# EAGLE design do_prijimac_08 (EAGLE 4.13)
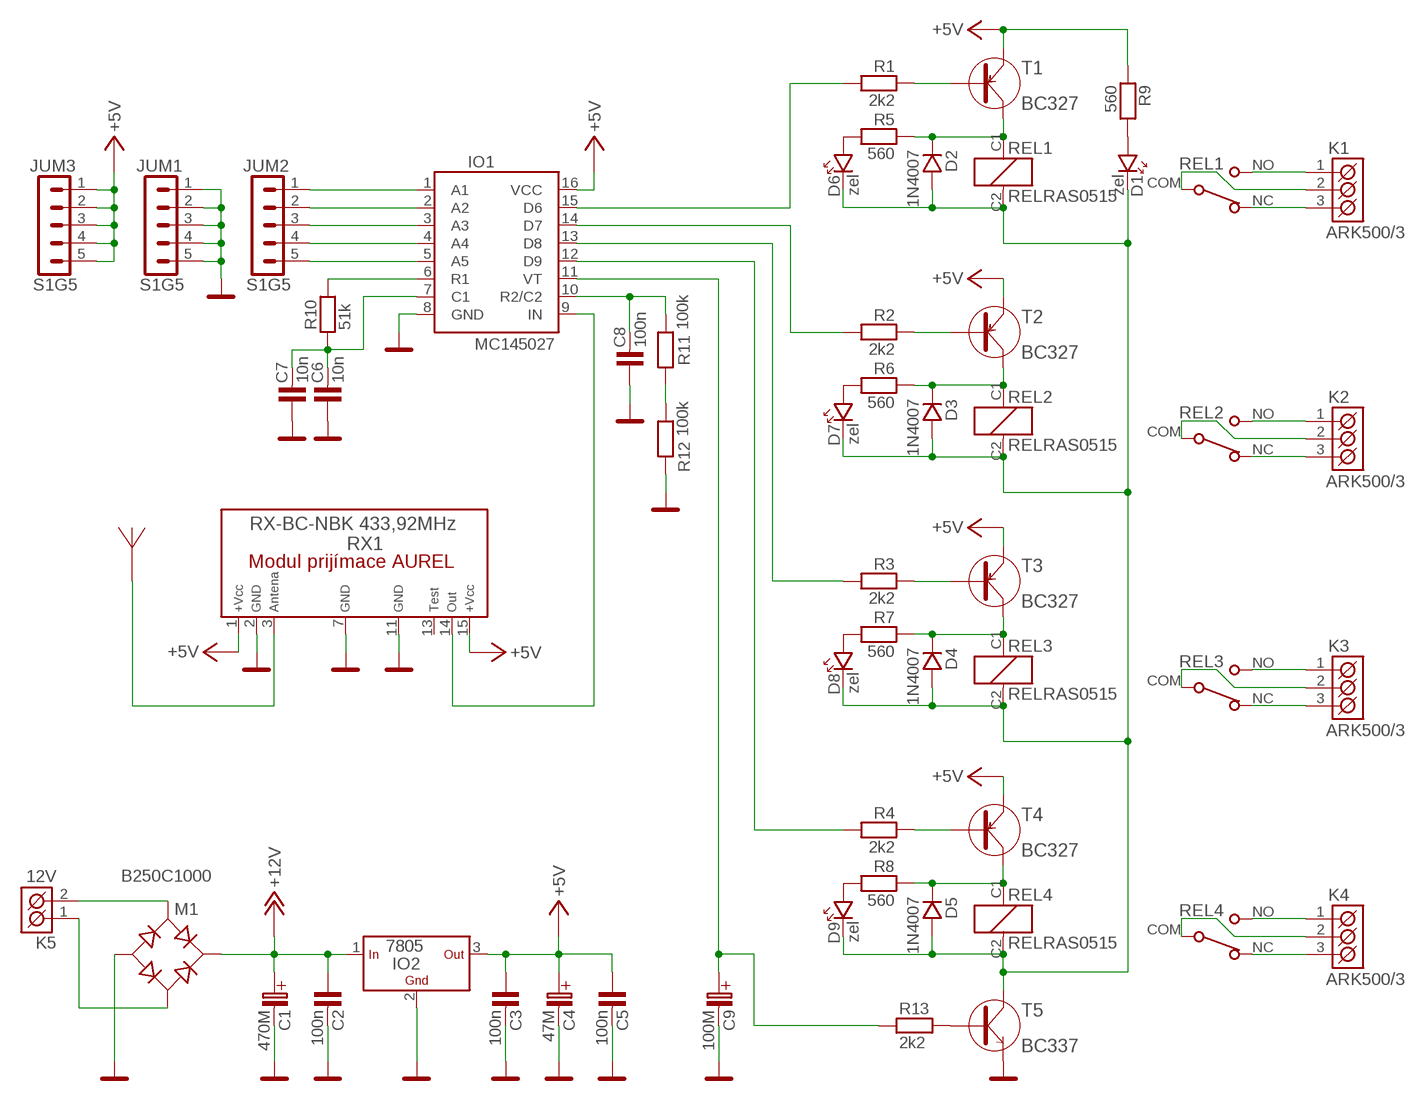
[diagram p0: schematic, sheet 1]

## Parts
ANT1  ANTENA  [PAD_1]
C1  470M  C-ELEKTROLYT_5  [C-EL_5]
C2  100n  C-KERAMIK_5  [C-5]
C3  100n  C-KERAMIK_5  [C-5]
C4  47M  C-ELEKTROLYT_2  [C-EL_2]
C5  100n  C-KERAMIK_SMD_1206  [1206]
C6  10n  C-KERAMIK_SMD_1206  [1206]
C7  10n  C-KERAMIK_SMD_1206  [1206]
C8  100n  C-KERAMIK_SMD_1206  [1206]
C9  100M  C-ELEKTROLYT_2  [C-EL_2]
D1  zel  LED_SMD_1206  [P1206]
D2  1N4007  1N4007_SMD_SM-1  [SM-1]
D3  1N4007  1N4007_SMD_SM-1  [SM-1]
D4  1N4007  1N4007_SMD_SM-1  [SM-1]
D5  1N4007  1N4007_SMD_SM-1  [SM-1]
D6  zel  LED_3  [LED_3]
D7  zel  LED_3  [LED_3]
D8  zel  LED_3  [LED_3]
D9  zel  LED_3  [LED_3]
IO1  MC145027  [DIL16]
IO2  7805  78_LEZ_LEZ  [TO-220]
JUM1  S1G5  S1G5_JUMP  [S1G5_JUM]
JUM2  S1G5  S1G5_JUMP  [S1G5_JUM]
JUM3  S1G5  S1G5_JUMP  [S1G5_JUM]
K1  ARK500/3  [ARK500/3]
K2  ARK500/3  [ARK500/3]
K3  ARK500/3  [ARK500/3]
K4  ARK500/3  [ARK500/3]
K5  12V  ARK500/2  [ARK500/2]
M1  B250C1000  BC1000  [DM_DB1]
R1  2k2  R_SMD_1206  [1206]
R2  2k2  R_SMD_1206  [1206]
R3  2k2  R_SMD_1206  [1206]
R4  2k2  R_SMD_1206  [1206]
R5  560  R_SMD_1206  [1206]
R6  560  R_SMD_1206  [1206]
R7  560  R_SMD_1206  [1206]
R8  560  R_SMD_1206  [1206]
R9  560  R_SMD_1206  [1206]
R10  51k  R_SMD_1206  [1206]
R11  100k  R_SMD_1206  [1206]
R12  100k  R_SMD_1206  [1206]
R13  2k2  R_SMD_1206  [1206]
REL1  RELRAS0515  RELRAS15  [RELE_RAS]
REL2  RELRAS0515  RELRAS15  [RELE_RAS]
REL3  RELRAS0515  RELRAS15  [RELE_RAS]
REL4  RELRAS0515  RELRAS15  [RELE_RAS]
RX1  RX-BC-NBK433  [RX-BC-NB]
T1  BC327  [TO-92]
T2  BC327  [TO-92]
T3  BC327  [TO-92]
T4  BC327  [TO-92]
T5  BC337  [TO-92]

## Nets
+5V: C3.1 C4.C+(C_EL+) C5.1 IO1.16(VCC) IO2.3(OUT) JUM3.1 JUM3.2 JUM3.3 JUM3.4 JUM3.5 R9.1 RX1.1(+5V) RX1.15(+5V) T1.3(E) T2.3(E) T3.3(E) T4.3(E)
+12V: C1.C+(C_EL+) C2.1 IO2.1(IN) M1.+
GND: C1.C-(C_EL-) C2.2 C3.2 C4.C-(C_EL-) C5.2 C6.1 C7.1 C8.1 C9.C-(C_EL-) IO1.8(GND) IO2.2(GND) JUM1.1 JUM1.2 JUM1.3 JUM1.4 JUM1.5 M1.- R12.1 RX1.2(GND) RX1.7(GND) RX1.11(GND) T5.3(E)
N$1: IO1.1(A1) JUM2.1
N$2: IO1.2(A2) JUM2.2
N$3: IO1.3(A3) JUM2.3
N$4: IO1.4(A4) JUM2.4
N$5: IO1.5(A5) JUM2.5
N$6: C6.2 C7.2 IO1.7(C1) R10.1
N$7: R11.1 R12.2
N$8: IO1.6(R1) R10.2
N$9: C8.2 IO1.10(R2/C2) R11.2
N$10: K5.1(K1) M1.AC2
N$11: K5.2(K2) M1.AC1
N$13: ANT1.1 RX1.3(ANTENA)
N$14: IO1.9(IN) RX1.14(OUT)
N$15: C9.C+(C_EL+) IO1.11(VT) R13.1
N$16: D1.A R9.2
N$21: R4.1 T4.2(B)
N$22: R3.1 T3.2(B)
N$23: R1.1 T1.2(B)
N$24: R2.1 T2.2(B)
N$25: IO1.15(D6) R1.2
N$26: IO1.14(D7) R2.2
N$27: IO1.13(D8) R3.2
N$28: IO1.12(D9) R4.2
N$32: K1.3(K3) REL1.NC(SW:NC)
N$33: K1.2(K2) REL1.COM(SW:COM)
N$34: K1.1(K1) REL1.NO(SW:NO)
N$35: K2.1(K1) REL2.NO(SW:NO)
N$36: K2.2(K2) REL2.COM(SW:COM)
N$37: K2.3(K3) REL2.NC(SW:NC)
N$41: D6.A R5.2
N$42: D7.A R6.2
N$43: D8.A R7.2
N$44: D9.A R8.2
N$45: K3.1(K1) REL3.NO(SW:NO)
N$46: K3.2(K2) REL3.COM(SW:COM)
N$47: K3.3(K3) REL3.NC(SW:NC)
N$51: K4.1(K1) REL4.NO(SW:NO)
N$52: K4.2(K2) REL4.COM(SW:COM)
N$53: K4.3(K3) REL4.NC(SW:NC)
N$58: D2.K R5.1 REL1.C1(RE:C1) T1.1(C)
N$61: R13.2 T5.2(B)
N$62: D1.K D2.A D3.A D4.A D5.A D6.K D7.K D8.K D9.K REL1.C2(RE:C2) REL2.C2(RE:C2) REL3.C2(RE:C2) REL4.C2(RE:C2) T5.1(C)
N$63: D3.K R6.1 REL2.C1(RE:C1) T2.1(C)
N$64: D4.K R7.1 REL3.C1(RE:C1) T3.1(C)
N$65: D5.K R8.1 REL4.C1(RE:C1) T4.1(C)
Unconnected: RX1.13(MER_BOD)

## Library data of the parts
ANT1 = #PaJa_15:ANTENA: SCH symbol - Anteny + pajeci bod na DPS
C1 C4 = #PaJa_15:C-ELEKTROLYT: Kondenzator - elektrolyticky
C2 C3 C5-C8 = #PaJa_15:C-KERAMIK: Kondenzator - keramicky
C9 = #PaJa_17:C-ELEKTROLYT: Kondenzator - elektrolyticky
D1 D6-D9 = #PaJa_15:LED: LED - jednobarevna
D2-D5 = #PaJa_15:1N4007: Usmernovaci dioda - 1A, 1000V
IO1 = #PaJa_15:MC145027
IO2 = #PaJa_15:78??: Stabilizátor - 1A a 1,5A ?? - napeti => 05, 06, 08, 09, 12, 15, 18, 20, 24 => 1,5A ?? - napeti => 10, 12, 15, 18 => 1A
JUM1-JUM3 = #PaJa_15:S1G5_JUMP: Radove konektory - koliky - 5x
K1-K4 = #PaJa_15:ARK500/3: Svorkovnice - roztec 5mm - trojita
K5 = #PaJa_15:ARK500/2: Svorkovnice - roztec 5mm - dvojita
M1 = #PaJa_16:B???C1000: Diodovy mustek - 250V nebo 380V, 1A
R1-R12 = #PaJa_15:R: Rezistor
R13 = #PaJa_16:R: Rezistor
REL1-REL4 = #PaJa_19:RELRAS??15: RELE - 1x prepinaci, 5V, 12V, 24V max. spinany proud = 15A
RX1 = #PaJa_16:RX-BC-NBK433: Modul prijimace AUREL - 433,92 MHz
T1-T4 = #PaJa_17:BC327: Tranzistor PNP - Univerzalni NF - Ic=0,5A
T5 = #PaJa_16:BC337: Tranzistor NPN - Univerzalni NF - Ic=0,5A

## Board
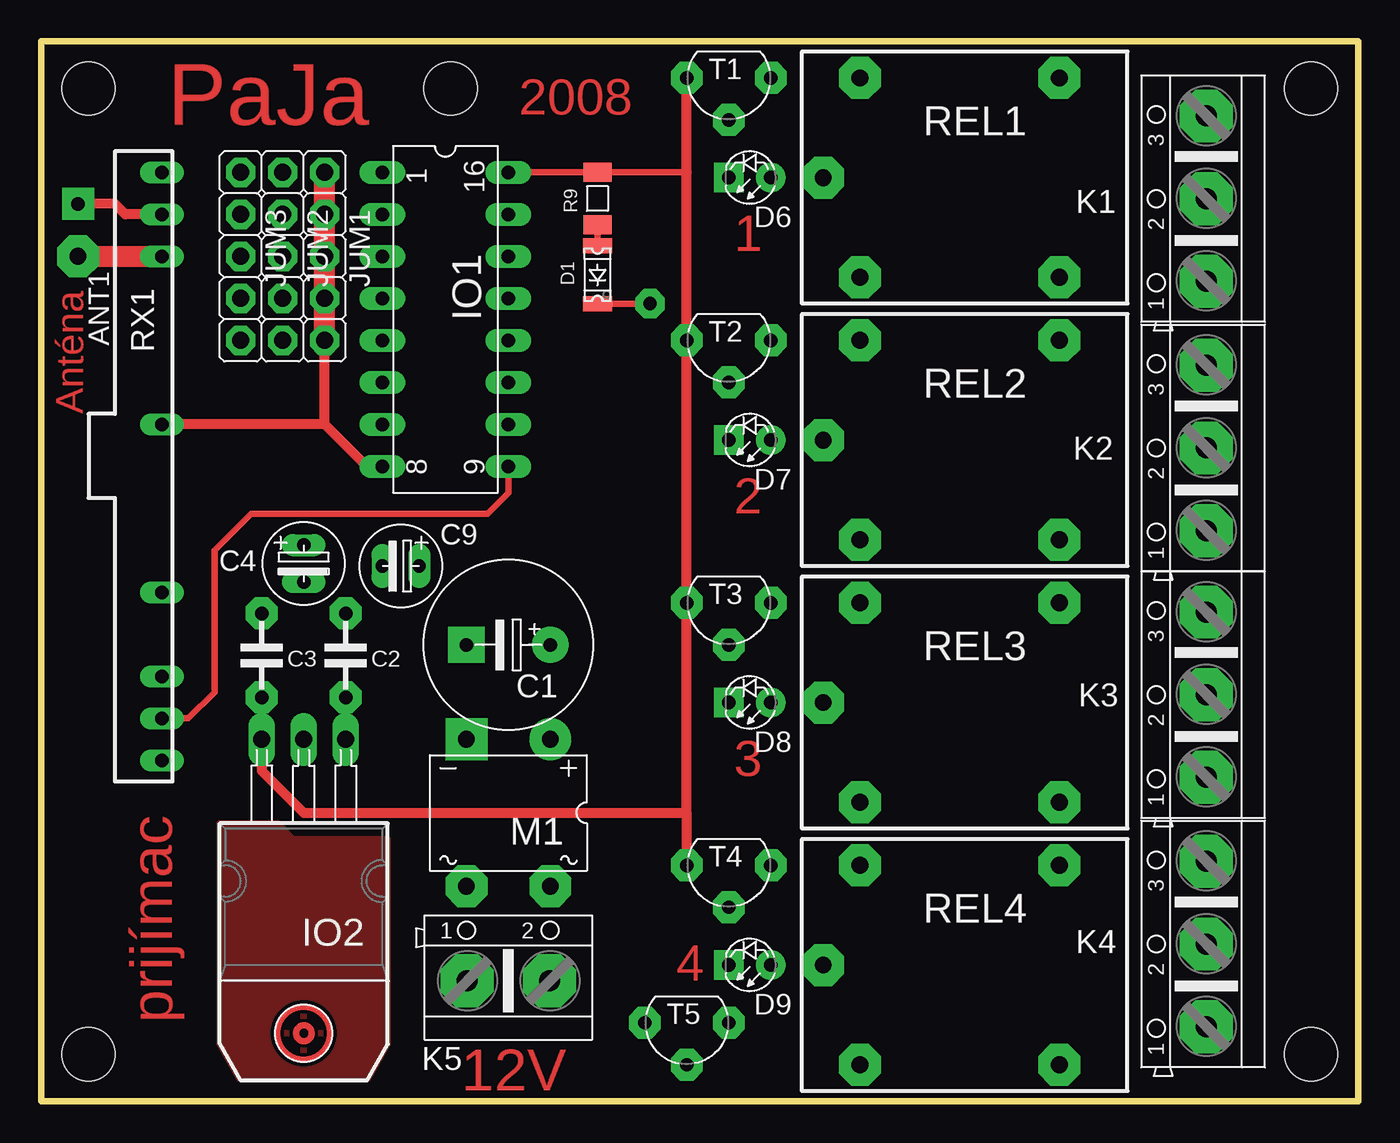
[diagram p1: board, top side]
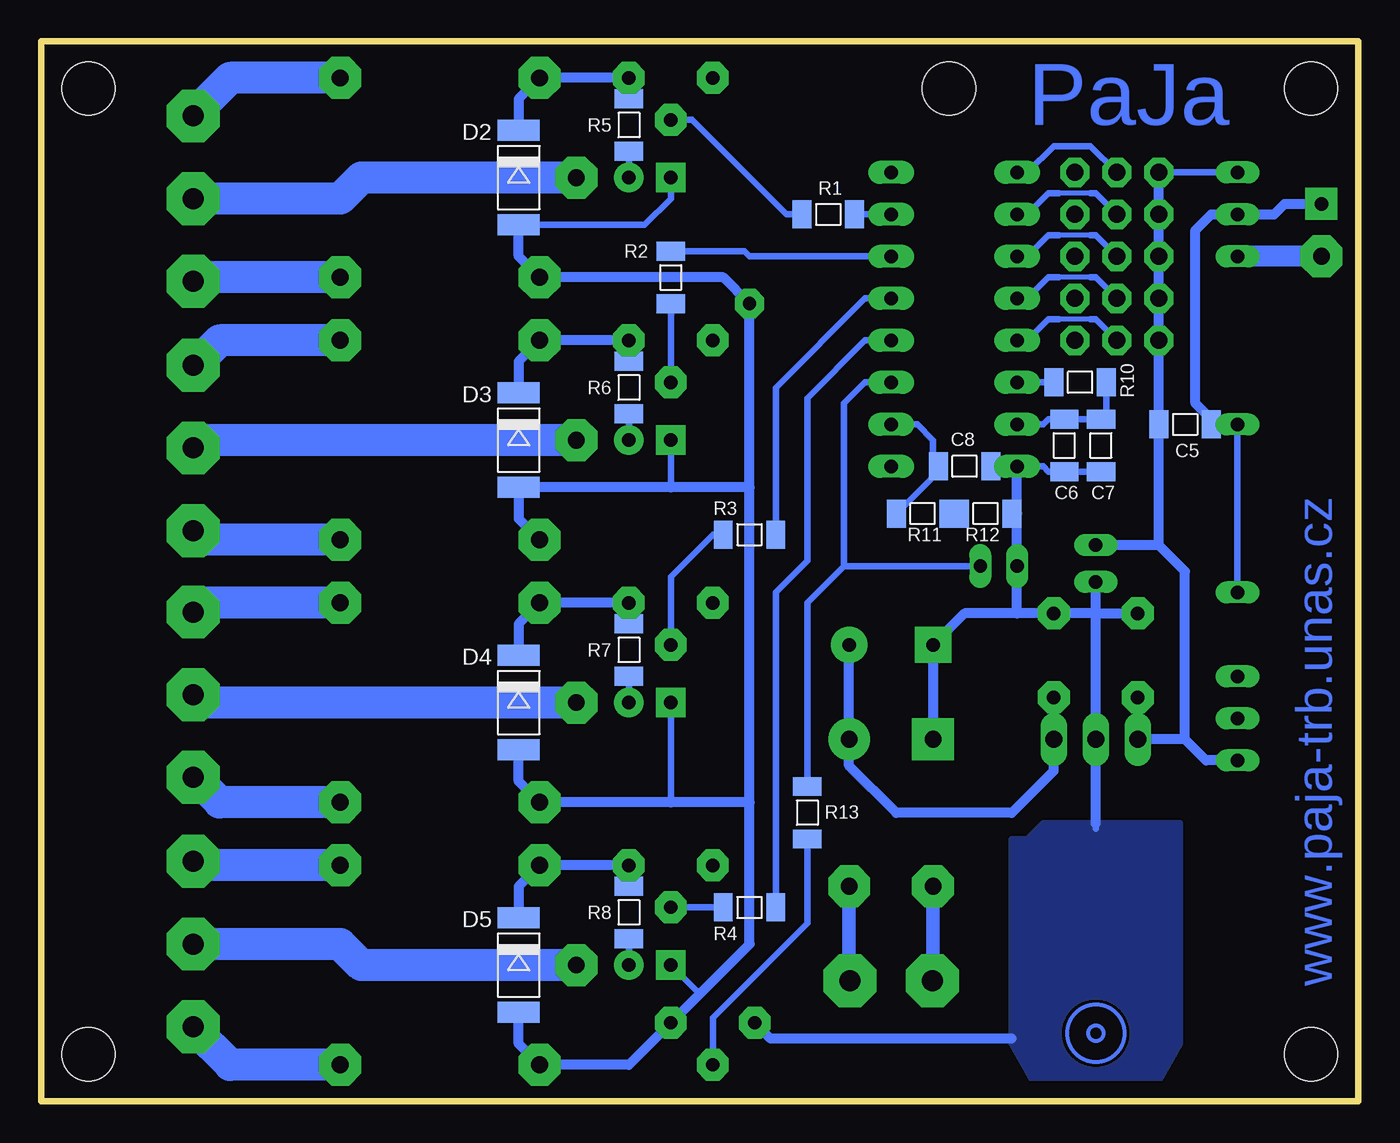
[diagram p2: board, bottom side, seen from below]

Size 79.68 x 64.12 mm. Coordinates in mm from the lower left corner, seen from the top.
Outline: 0,0 79.68,0 79.68,64.12 0,64.12 0,0
Copper layers (1*16): Top 0.035mm / dielectric 1.5mm / Bottom 0.035mm
Design rules "default": minimum track width 10mil, minimum drill 24mil, track to track 8mil, track to pad 8mil, pad to pad 8mil, via to via 8mil, smd to smd 8mil, copper to edge 40mil, drill to drill 8mil, minimum pad ring 10mil, minimum via ring 8mil, stop-mask expansion 4mil, vias tented up to drill 0mil, thermal gap 10mil
Holes 3.2 mm at 2.86,2.86 2.86,61.28 76.83,61.28 76.83,2.86 24.77,61.28

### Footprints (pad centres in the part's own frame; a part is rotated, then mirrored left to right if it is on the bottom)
PAD_1 = drill 1.016 pad 2.54 octagon: 1 0,0
C-EL_5 = drill 0.813 pad 2.184 round: C+ -2.54,0 | drill 0.813 pad 2.184 square: C- 2.54,0
C-5 = drill 0.813 pad 1.93 octagon: 1 -2.54,0; 2 2.54,0
C-EL_2 = drill 0.813 pad 1.27 long: C+ 0,0; C- 2.223,0
1206 = smd 1.143 x 1.702: 1 -1.587,0; 2 1.587,0
P1206 = smd 0.914 x 1.778: A 1.905,0; K -1.587,0
SM-1 = smd 1.27 x 2.54: A 2.54,0; K -3.175,0
LED_3 = drill 0.813 pad 1.778 round: A -1.27,0 | drill 0.813 pad 1.778 square: K 1.27,0
DIL16 = drill 0.813 pad 1.4 long: 1 -8.89,-3.81; 2 -6.35,-3.81; 3 -3.81,-3.81; 4 -1.27,-3.81; 5 1.27,-3.81; 6 3.81,-3.81; 7 6.35,-3.81; 8 8.89,-3.81; 9 8.89,3.81; 10 6.35,3.81; 11 3.81,3.81; 12 1.27,3.81; 13 -1.27,3.81; 14 -3.81,3.81; 15 -6.35,3.81; 16 -8.89,3.81
TO-220 = drill 1.016 pad 1.6 long: 1 -2.54,0; 2 0,0; 3 2.54,0
S1G5_JUM = drill 1.016 pad 1.778 octagon: 1 -5.08,0; 2 -2.54,0; 3 0,0; 4 2.54,0; 5 5.08,0
ARK500/3 = drill 1.27 pad 3.2 octagon: 1 -5,0; 2 0,0; 3 5,0
ARK500/2 = drill 1.27 pad 3.2 octagon: 1 -2.5,0; 2 2.5,0
DM_DB1 = drill 1.016 pad 2.54 round: + -2.54,-4.445 | drill 1.016 pad 2.54 square: - 2.54,-4.445 | drill 1.016 pad 2.54 octagon: AC1 -2.54,4.445; AC2 2.54,4.445
RELE_RAS = drill 1.016 pad 2.54 octagon: C1 -6.35,6.032; C2 -6.35,-6.032; COM -8.572,0; NC 5.715,6.032; NO 5.715,-6.032
RX-BC-NB = drill 0.813 pad 1.27 long: 1 -17.78,0; 2 -15.24,0; 3 -12.7,0; 7 -2.54,0; 11 7.62,0; 13 12.7,0; 14 15.24,0; 15 17.78,0
TO-92 = drill 0.813 pad 1.93 octagon: 1 0,2.54; 2 2.54,0; 3 0,-2.54

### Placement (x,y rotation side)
ANT1  2.22,51.12 0 top
C1  28.26,27.62 180 top
C2  18.41,26.99 90 top
C3  13.34,26.99 90 top
C4  15.88,33.66 270 top
C5  10.48,40.96 0 bottom
C6  17.78,39.69 90 bottom
C7  15.56,39.69 90 bottom
C8  23.81,38.42 180 bottom
C9  22.86,32.38 180 top
D1  33.66,49.85 90 top
D2  50.8,55.56 270 bottom
D3  50.8,39.69 270 bottom
D4  50.8,23.81 270 bottom
D5  50.8,7.94 270 bottom
D6  42.86,55.88 180 top
D7  42.86,40.01 180 top
D8  42.86,24.13 180 top
D9  42.86,8.26 180 top
IO1  24.45,47.31 270 top
IO2  15.88,21.91 180 top
JUM1  17.14,51.12 270 top
JUM2  14.61,51.12 270 top
JUM3  12.06,51.12 270 top
K1  70.48,54.61 90 top
K2  70.48,39.53 90 top
K3  70.48,24.61 90 top
K4  70.48,9.52 90 top
K5  28.26,7.3 0 top
M1  28.26,17.46 180 top
R1  32.07,53.66 0 bottom
R2  41.59,49.85 90 bottom
R3  36.83,34.29 0 bottom
R4  36.83,11.75 0 bottom
R5  44.13,59.05 270 bottom
R6  44.13,43.18 270 bottom
R7  44.13,27.3 270 bottom
R8  44.13,11.43 270 bottom
R9  33.66,54.61 270 top
R10  16.83,43.5 180 bottom
R11  26.35,35.56 180 bottom
R12  22.54,35.56 180 bottom
R13  33.34,17.46 270 bottom
REL1  55.88,55.88 0 top
REL2  55.88,40.01 0 top
REL3  55.88,24.13 0 top
REL4  55.88,8.26 0 top
RX1  7.3,38.42 270 top
T1  41.59,61.91 270 top
T2  41.59,46.04 270 top
T3  41.59,30.16 270 top
T4  41.59,14.29 270 top
T5  39.05,4.76 270 top

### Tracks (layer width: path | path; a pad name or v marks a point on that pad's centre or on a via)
+5V
  Top 0.406: IO1.16 R9.1 39.05,56.2
  Top 0.61: 39.05,17.46 15.88,17.46 13.34,20 IO2.3 | T1.3 39.05,56.2 T2.3 T3.3 39.05,17.46 | 39.05,17.46 T4.3
  Bottom 0.406: JUM3.1 RX1.1
  Bottom 0.61: JUM3.5 JUM3.4 JUM3.3 JUM3.2 JUM3.1 | RX1.15 9.21,20.64 10.48,21.91 | 10.48,21.91 10.48,32.07 12.06,33.66 | C3.1 IO2.3 10.48,21.91 | 12.06,33.66 C4.C+ | 12.06,33.66 C5.1 | C5.1 JUM3.5 | C5.1 JUM3.5
+12V
  Bottom 0.61: C1.C+ M1.+ 30.8,20.32 27.94,17.46 20.95,17.46 18.41,20 IO2.1 C2.1
GND  (via drill 0.81 pad 1.93)
  Top 0.61: 17.14,40.96 JUM1.5 | 17.14,40.96 19.68,38.42 IO1.8 | 17.14,40.96 RX1.7 | RX1.2 5.08,53.66 4.45,54.29 v2.22,54.29
  Top 1.27: JUM1.1 JUM1.2 JUM1.3 JUM1.4 JUM1.5
  Bottom 0.406: C7.1 C6.1 18.73,38.1 19.05,38.42 IO1.8 C8.1 | RX1.11 RX1.7 8.57,40.96 C5.2 | 15.88,16.83 15.88,16.51
  Bottom 0.61: 15.88,16.83 IO2.2 15.88,29.53 | 15.88,29.53 C4.C- | T5.3 35.56,3.81 20.95,3.81 | 15.88,29.53 C3.2 | 15.88,29.53 C2.2 20.64,29.53 | M1.- C1.C- 23.81,29.53 20.64,29.53 | 20.64,29.53 C9.C- 20.64,35.56 | 20.64,35.56 R12.1 | 20.64,35.56 IO1.8 | 8.57,40.96 9.84,42.23 9.84,52.7 8.89,53.66 RX1.2 5.08,53.66 4.45,54.29 v2.22,54.29
  pour Bottom: 10.79,16.83 19.05,16.83 20,15.88 20.95,15.88 20.95,3.49 19.68,1.27 12.06,1.27 10.79,3.49
N$1
  Bottom 0.406: IO1.1 20,56.2 18.41,57.78 16.19,57.78 JUM2.1
N$2
  Bottom 0.305: 16.19,54.93 18.1,54.93
  Bottom 0.406: IO1.2 20,53.66 18.73,54.93 18.1,54.93 | JUM2.2 15.88,54.93 16.19,54.93
N$3
  Bottom 0.305: 16.19,52.39 18.1,52.39
  Bottom 0.406: IO1.3 20,51.12 18.73,52.39 18.1,52.39 | JUM2.3 15.88,52.39 16.19,52.39
N$4
  Bottom 0.305: 16.19,49.85 18.1,49.85
  Bottom 0.406: IO1.4 20,48.58 18.73,49.85 18.1,49.85 | JUM2.4 15.88,49.85 16.19,49.85
N$5
  Bottom 0.305: 16.19,47.31 18.1,47.31
  Bottom 0.406: IO1.5 20,46.04 18.73,47.31 18.1,47.31 | JUM2.5 15.88,47.31 16.19,47.31
N$6
  Bottom 0.406: R10.1 15.24,41.27 C7.2 C6.2 18.73,41.27 19.05,40.96 IO1.7
N$7
  Bottom 0.406: R12.2 R11.1
N$8
  Bottom 0.406: R10.2 IO1.6
N$9
  Bottom 0.406: R11.2 25.4,38.1 C8.2 25.72,38.42 25.72,40.01 26.67,40.96 IO1.10
N$10
  Bottom 0.813: K5.1 25.76,7.58 25.72,7.62 M1.AC2
N$11
  Bottom 0.813: K5.2 30.8,7.3 M1.AC1
N$12
  pour Top: 10.79,16.83 14.29,16.83 15.24,15.88 20.95,15.88 20.95,3.49 19.68,1.27 12.06,1.27 10.79,3.49
N$13
  Top 1.27: ANT1.1 RX1.3
  Bottom 1.27: ANT1.1 RX1.3
N$14
  Top 0.406: IO1.9 28.26,36.83 26.99,35.56 12.7,35.56 10.48,33.34 10.48,24.77 8.89,23.18 RX1.14
N$15
  Bottom 0.406: IO1.11 29.84,43.5 31.11,42.23 31.11,32.38 | 31.11,32.38 C9.C+ | R13.1 33.34,30.16 31.11,32.38
N$16
  Top 0.406: D1.A | D1.A R9.2
N$21
  Bottom 0.406: R4.1 T4.2
N$22
  Bottom 0.406: R3.1 39.05,34.29 41.59,31.75 T3.2
N$23
  Bottom 0.406: R1.1 34.61,53.66 40.32,59.37 T1.2
N$24
  Bottom 0.406: T2.2 R2.1
N$25
  Bottom 0.406: IO1.15 R1.2
N$26
  Bottom 0.406: R2.2 37.15,51.44 36.83,51.12 IO1.14
N$27
  Bottom 0.406: IO1.13 29.84,48.58 35.24,43.18 R3.2
N$28
  Bottom 0.406: R4.2 35.24,30.8 33.34,32.7 33.34,42.55 29.84,46.04 IO1.12
N$32
  Bottom 1.93: K1.3 70.48,59.69 68.26,61.91 REL1.NC
N$33
  Bottom 1.93: REL1.COM 60.33,55.88 61.59,54.61 K1.2
N$34
  Bottom 1.93: K1.1 70.48,49.53 70.17,49.85 REL1.NO
N$35
  Bottom 1.93: K2.1 70.48,34.61 69.85,33.97 REL2.NO
N$36
  Bottom 1.93: K2.2 70.48,39.37 69.85,40.01 REL2.COM
N$37
  Bottom 1.93: K2.3 70.48,44.45 68.9,46.04 REL2.NC
N$41
  Bottom 0.406: D6.A R5.2
N$42
  Bottom 0.406: D7.A R6.2
N$43
  Bottom 0.406: D8.A R7.2
N$44
  Bottom 0.406: D9.A R8.2
N$45
  Bottom 1.93: K3.1 70.48,19.68 68.9,18.1 REL3.NO
N$46
  Bottom 1.93: K3.2 70.48,24.45 70.17,24.13 REL3.COM
N$47
  Bottom 1.93: K3.3 70.48,29.53 69.85,30.16 REL3.NC
N$51
  Bottom 1.93: K4.1 70.48,4.45 68.26,2.22 REL4.NO
N$52
  Bottom 1.93: REL4.COM 60.33,8.26 61.59,9.53 K4.2 | K4.2
N$53
  Bottom 1.93: K4.3 70.48,14.61 70.17,14.29 REL4.NC
N$58
  Bottom 0.406: R5.1 T1.1
  Bottom 0.61: D2.K 50.8,60.64 REL1.C1 T1.1
N$61
  Bottom 0.406: R13.2 33.34,10.79 39.05,5.08 T5.2
N$62  (via drill 0.81 pad 1.78)
  Top 0.406: v36.83,48.26 D1.K
  Bottom 0.406: D9.K 40.01,6.67 39.69,6.67 | D6.K 41.59,54.61 43.18,53.02 D2.A | 41.59,37.15 D7.K | 41.59,18.1 D8.K
  Bottom 0.61: D2.A 50.8,51.12 REL1.C2 38.42,49.85 v36.83,48.26 36.83,37.15 | REL2.C2 50.8,35.24 D3.A 41.59,37.15 36.83,37.15 | D4.A 50.8,19.37 REL3.C2 41.59,18.1 36.83,18.1 | D5.A 50.8,3.49 REL4.C2 44.13,2.22 T5.1 39.69,6.67 36.83,9.53 36.83,18.1 | 36.83,18.1 36.83,37.15
N$63
  Bottom 0.406: R6.1 T2.1
  Bottom 0.61: D3.K 50.8,44.77 REL2.C1 T2.1
N$64
  Bottom 0.406: T3.1 R7.1
  Bottom 0.61: T3.1 REL3.C1 50.8,28.89 D4.K
N$65
  Bottom 0.406: T4.1 R8.1
  Bottom 0.61: T4.1 REL4.C1 50.8,13.02 D5.K
(copper drawn outside any net)
  shapes: Bottom circle x2, Top circle x2

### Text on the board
Top: 2008 | PaJa | 1 | Anténa | 2 | 3 | 4 | prijímac | 12V
Bottom: PaJa | www.paja-trb.unas.cz
Reference: Relé 1 | Prijímá | 433,92MHz | Relé 2 | Relé 3 | Dálkové ovládání | Relé 4 | PaJa | 2008
Popisy: NC | Com | NO | NC | Com | NO | NC | Com | NO | NC | Com | NO
Zapojeni: NC | COM | NO | NC | COM | NO | NC | COM | NO | NC | COM | NO | +-12V (= nebo ~)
